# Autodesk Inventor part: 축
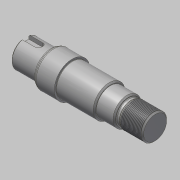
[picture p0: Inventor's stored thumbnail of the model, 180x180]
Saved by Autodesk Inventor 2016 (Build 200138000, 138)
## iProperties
Created: 2019-05
Part Number: 축
Material: 강철, 연강
Document SubType Name: Modeling
Designer: mduedu
Density: 1 g/cm^3
Appearance: 강철
Author: mduedu
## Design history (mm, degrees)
sketch "스케치1"
  geometry: L1 (0, 0)-(20, 0); L2 (20, 0)-(20, 11); L3 (20, 11)-(0, 11); L4 (0, 11)-(0, 0); L5 (20, 0)-(37, 0); L6 (37, 0)-(37, 14); L7 (37, 14)-(20, 14); L8 (20, 14)-(20, 0); L9 (37, 0)-(67, 0); L10 (67, 0)-(67, 12.5); L11 (67, 12.5)-(37, 12.5); L12 (37, 12.5)-(37, 0); L13 (67, 0)-(81, 0); L14 (81, 0)-(81, 11); L15 (81, 11)-(67, 11); L16 (67, 11)-(67, 0); L17 (81, 0)-(102, 0); L18 (102, 0)-(102, 10); L19 (102, 10)-(81, 10); L20 (81, 10)-(81, 0)
  constraints: 40 end point, 10 parallel, 5 horizontal, 5 perpendicular
  dimensions: "d0" = 102 distance between parallel lines of L18 L4; "d2" = 21 distance of L18.end L19.end; "d3" = 14 distance of L14.end L15.end; "d4" = 30 distance of L10.end L11.end; "d5" = 17 distance of L6.end L7.end; "d6" = 22 diameter of L3 L1; "d7" = 28 diameter of L7 L5; "d8" = 25 diameter of L11 L9; "d9" = 22 diameter of L15 L13; "d10" = 20 diameter of L19 L17
revolve "회전1" sketch "스케치1" stored, may be unused: angle "d11" = 90 deg
chamfer "모따기1" distance "d12" = 2.34; stored, may be unused: second distance "d13" = 2, angle "d14" = 30 deg
fillet "모깎기1" dims "d15" = 2, "d16" = 1
fillet "모깎기2" dims "d17" = 0.3
chamfer "모따기2" distance "d18" = 1; stored, may be unused: second distance "d19" = 2, angle "d20" = 30 deg
sketch "스케치2"
  geometry: L1 (102, -10)-(81, -10) reference; L2 (81, -10)-(81, -11) reference; L3 (81, -11)-(67, -11) reference; L4 (67, -11)-(67, -11.5) reference; L5 (67, -11.5)-(66, -12.5) reference; L6 (66, -12.5)-(37.3, -12.5) reference; L7 (37, -12.8)-(37, -14) reference; L8 (37, -14)-(22.876, -14) reference; L9 (21.876, -13.732)-(20.5, -12.938) reference; L10 (20, -12.072)-(20, -11) reference; L11 (20, -11)-(0, -11) reference; L12 (0, -11)-(0, 11) reference; L13 (0, 11)-(20, 11) reference; L14 (20, 11)-(20, 12.072) reference; L15 (20.5, 12.938)-(21.876, 13.732) reference; L16 (22.876, 14)-(37, 14) reference; L17 (37, 14)-(37, 12.8) reference; L18 (37.3, 12.5)-(66, 12.5) reference; L19 (66, 12.5)-(67, 11.5) reference; L20 (67, 11.5)-(67, 11) reference; L21 (67, 11)-(81, 11) reference; L22 (81, 11)-(81, 10) reference; L23 (81, 10)-(102, 10) reference; L24 (102, 10)-(102, -10) reference; L25 (0, 0)-(102, 0); L26 (81, 10)-(84.726, 10); L27 (83.34, 9.2)-(81, 9.2); L28 (81, 9.2)-(81, 10); L29 (84.726, 10)-(83.34, 9.2); A1 r 0.3 centre (37.3, -12.8) between (37.3, -12.5) and (37, -12.8) reference; A2 r 2 centre (22.876, -12) between (21.876, -13.732) and (22.876, -14) reference; A3 r 1 centre (21, -12.072) between (20, -12.072) and (20.5, -12.938) reference; A4 r 1 centre (21, 12.072) between (20.5, 12.938) and (20, 12.072) reference; A5 r 2 centre (22.876, 12) between (22.876, 14) and (21.876, 13.732) reference; A6 r 0.3 centre (37.3, 12.8) between (37, 12.8) and (37.3, 12.5) reference
  constraints: 10 end point, 1 horizontal, 1 midpoint, 1 parallel, 1 vertical
  dimensions: "d21" = 18.4 diameter of L27 L25; "d23" = 2.34 distance of L27.start L27.end; "d24" = 30 deg angle of L23 L29
revolve "회전2" sketch "스케치2" stored, may be unused: angle "d25" = 90 deg
fillet "모깎기3" dims "d26" = 0.6
chamfer "모따기3" distance "d27" = 1; stored, may be unused: second distance "d28" = 2, angle "d29" = 30 deg
feature "스레드1" dims "d30" = 10, "d31" = 0
chamfer "모따기4" distance "d32" = 1; stored, may be unused: second distance "d33" = 2, angle "d34" = 30 deg
node "작업 평면1"
sketch "스케치3"
  geometry: L1 (10, -3)-(-1, -3); L2 (-1, -3)-(-1, 3); L3 (-1, 3)-(10, 3); L4 (10, 3)-(10, -3); 3 further points
  constraints: 8 end point, 2 midpoint, 2 parallel, 1 coincident, 1 horizontal, 1 perpendicular, 1 vertical alignment, 2 other
  dimensions: "d35" = 14 dimension on L4; "d37" = 6 distance between parallel lines of L3 L1
extrude "돌출1" cut sketch "스케치3" distance "d38" = 3.5; taper "d39" = 0 deg
chamfer "모따기5" distance "d40" = 1; stored, may be unused: second distance "d41" = 2, angle "d42" = 30 deg
node "솔리드1"
node "절단 모서리 투영1"
